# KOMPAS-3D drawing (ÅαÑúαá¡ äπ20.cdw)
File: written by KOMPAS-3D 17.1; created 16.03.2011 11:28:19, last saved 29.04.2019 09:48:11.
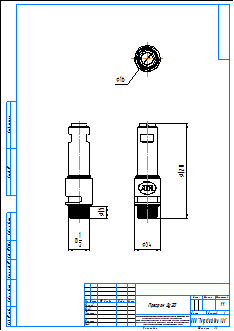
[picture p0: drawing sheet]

Title block, sheet 1: name: Прегран Ду20; material: Внимание! Данный продукт является объектом авторского права ООО «Торговый Дом АДЛ». / Запрещается изменение, копирование, распространение / (в том числе путем копирования на другие сайты и ресурсы в Интернете) / или любое иное использование информации и объектов без предварительного / согласия правообладателя (ООО «Торговый Дом АДЛ»).; scale: 1:1; sheets: 1; organisation: ООО "Торговый дом АДЛ"; sheet format: A3; stored path: C:\Users\tra\Desktop\2д чертежи\Предохранительные клапаны ПРЕГРАН\ПРЕГРАН 495\ПРЕГРАН КПП 495-05-25-ОМЗ\KOMPAS 2D\Прегран Ду20.cdw

Views: Спереди 1, Проекционный вид 2, Проекционный вид 3
Dimensions and other numbers on the sheet: 34; 15; 120; 16; 1:1; 1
